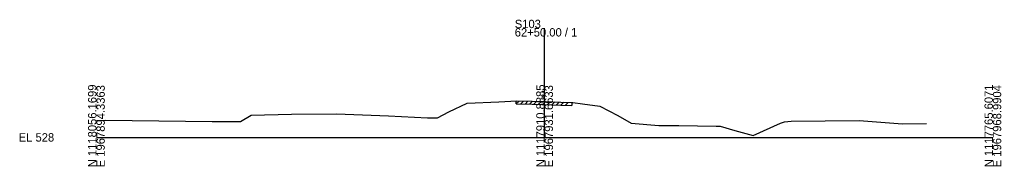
# Model space of a CAD drawing. Extents: x 974 to 1303, y 990 to 14518.
# Drawn here: x 974.3 to 1302.8, y 6990.3 to 7039.4 of the extents above; entities that cross this region are included whole.
import ezdxf

# ---------------------------------------------------------------- set-up
doc = ezdxf.new("R2010")
doc.units = 0
for name, color, linetype in [('Level 10', 7, 'Continuous'), ('Level 60', 7, 'Continuous'), ('Level 61', 7, 'Continuous'), ('Level 63', 7, 'Continuous')]:
    doc.layers.add(name, color=color, linetype=linetype)

msp = doc.modelspace()

# ---------------------------------------------------------------- linework, layer by layer
at = {"layer": 'Level 60'}
for p, q in [((1117.95, 7008.58), (1124.12, 7011.43)), ((1124.12, 7011.43), (1134.71, 7011.91)), ((1134.71, 7011.91), (1140.71, 7012.18)), ((1140.71, 7012.18), (1145.83, 7012.1)), ((1145.83, 7012.1), (1149.06, 7012.04)), ((1149.06, 7012.04), (1150, 7012.01)), ((1150, 7012.01), (1155.44, 7011.81)), ((1155.44, 7011.81), (1159.39, 7011.64)), ((1159.39, 7011.64), (1162.63, 7011.25)), ((1162.63, 7011.25), (1168.51, 7010.43)), ((1051.79, 7007.46), (1065.32, 7007.73)), ((1065.32, 7007.73), (1080.35, 7007.91)), ((1080.35, 7007.91), (1097.7, 7007.26)), ((1114.11, 7006.55), (1117.95, 7008.58)), ((1168.51, 7010.43), (1174.47, 7007.3)), ((1000, 7005.63), (1001.34, 7005.64)), ((1001.34, 7005.64), (1002.99, 7005.75)), ((1002.99, 7005.75), (1038.78, 7005.32)), ((1038.78, 7005.32), (1048.24, 7005.37)), ((1048.24, 7005.37), (1051.79, 7007.46)), ((1097.7, 7007.26), (1110.79, 7006.57)), ((1110.79, 7006.57), (1114.11, 7006.55)), ((1174.47, 7007.3), (1178.91, 7004.71)), ((1178.91, 7004.71), (1188.26, 7003.99)), ((1219.73, 7000.58), (1228.98, 7004.73)), ((1228.98, 7004.73), (1230.3, 7005.19)), ((1230.3, 7005.19), (1232.46, 7005.47)), ((1232.46, 7005.47), (1255.26, 7005.67)), ((1255.26, 7005.67), (1269.78, 7004.57)), ((1269.78, 7004.57), (1277.74, 7004.65)), ((1188.26, 7003.99), (1194.93, 7003.94)), ((1194.93, 7003.94), (1207.45, 7003.8)), ((1207.45, 7003.8), (1208.75, 7003.76)), ((1208.75, 7003.76), (1213.66, 7002.34)), ((1213.66, 7002.34), (1219.73, 7000.58))]:
    msp.add_line(p, q, dxfattribs=at)
at = {"layer": 'Level 61'}
for p, q in [((1140.43, 7011.17), (1141.43, 7012.17)), ((1140.43, 7011.17), (1140.43, 7012.17)), ((1140.43, 7011.17), (1140.71, 7011.18)), ((1140.71, 7011.18), (1145.83, 7011.1)), ((1141.93, 7011.16), (1142.91, 7012.15)), ((1143.43, 7011.14), (1144.41, 7012.12)), ((1144.93, 7011.11), (1145.91, 7012.1)), ((1145.83, 7011.1), (1149.06, 7011.04)), ((1146.43, 7011.09), (1147.41, 7012.07)), ((1147.93, 7011.06), (1148.91, 7012.04)), ((1149.06, 7011.04), (1150, 7011.01)), ((1149.43, 7011.03), (1150.4, 7011.99)), ((1150, 7011.01), (1155.44, 7010.81)), ((1150.93, 7010.97), (1151.9, 7011.94)), ((1152.43, 7010.92), (1153.4, 7011.89)), ((1153.93, 7010.87), (1154.9, 7011.83)), ((1155.43, 7010.81), (1156.39, 7011.77)), ((1156.93, 7010.75), (1157.89, 7011.71)), ((1159.08, 7011.66), (1159.08, 7010.66)), ((1155.44, 7010.81), (1159.08, 7010.66))]:
    msp.add_line(p, q, dxfattribs=at)
at = {"layer": 'Level 63'}
for p, q in [((1150, 7000), (1150, 7036.55)), ((1000, 7000), (1150, 7000)), ((1150, 7000), (1300, 7000))]:
    msp.add_line(p, q, dxfattribs=at)

# ---------------------------------------------------------------- texts
at = {"layer": 'Level 10'}
msp.add_text('540.01', height=0.9, rotation=90, dxfattribs=at).set_placement((1149.95, 7012.51))
at = {"layer": 'Level 63'}
for s, p in [('S103', (1140, 7036.55)), ('62+50.00 / 1', (1140, 7033.75)), ('EL 528', (974, 6998.6))]:
    msp.add_text(s, height=2.8, dxfattribs=at).set_placement(p)
for s, p in [('N 1118056.1699', (1000, 6990)), ('N 1117910.8885', (1150, 6990)), ('N 1117765.6071', (1300, 6990)), ('E 1967894.3363', (1002.8, 6990)), ('E 1967931.6633', (1152.8, 6990)), ('E 1967968.9904', (1302.8, 6990))]:
    msp.add_text(s, height=2.8, rotation=90, dxfattribs=at).set_placement(p)

doc.saveas('drawing.dxf')
